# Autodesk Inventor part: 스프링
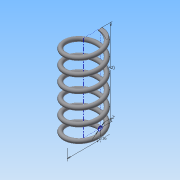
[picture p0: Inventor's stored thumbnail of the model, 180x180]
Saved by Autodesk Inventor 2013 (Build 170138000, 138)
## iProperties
Created: 2016-04
Part Number: 스프링
Material: 일반
Document SubType Name: Modeling
Designer: Administrator
Density: 1 g/cm^3
Mass: -0.00966318 g
Surface Area: 18.9934 cm^2
Volume: -0.00966318 cm^3
Author: Administrator
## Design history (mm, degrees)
sketch "스케치1"
  geometry: L1 (0, 0)-(8, 0); L2 (8, 0)-(8, 42); L3 (8, 42)-(0, 42); L4 (0, 42)-(0, 0); C1 r 1 at (8, 0)
  constraints: 8 end point, 2 parallel, 1 centre point, 1 coincident, 1 horizontal, 1 perpendicular
  dimensions: "d0" = 2 diameter of C1; "d2" = 16 diameter of L1.end L4; "d3" = 42 distance of L1.end L2.end (derived)
feature "코일1" sketch "스케치1" pitch "d4" = 10; turns "d6" = 6; dims "d5" = 42 (= d3), "d7" = 0, angle "d8" = 90 deg, angle "d9" = 90 deg, "d10" = 0, "d11" = 0
sketch "스케치2"
  geometry: L1 (0, 9)-(0, 7) reference; L2 (0, 9)-(0, 7) reference; 1 further point
  constraints: 2 vertical alignment
extrude "돌출1" cut sketch "스케치2" stored distance "d12" = 10; taper "d13" = 0 deg
node "작업 평면1"
sketch "스케치3"
  geometry: L1 (0, 7)-(0, 9) reference; 1 further point
  constraints: 1 vertical alignment
extrude "돌출2" cut sketch "스케치3" stored distance "d14" = 10; taper "d15" = 0 deg
node "솔리드1"
node "절단 모서리 투영1"
node "절단 모서리 투영2"
node "절단 모서리 투영3"
